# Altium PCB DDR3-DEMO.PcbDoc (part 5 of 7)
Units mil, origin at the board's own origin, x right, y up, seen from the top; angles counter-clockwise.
Board outline 2827 x 2165.35 mil, 8 copper layers (TOP, GND02, ART03, ART04, PWR05, ART06, GND07, BOTTOM); 111 components, 133 nets, 5542 pads, 873 vias.
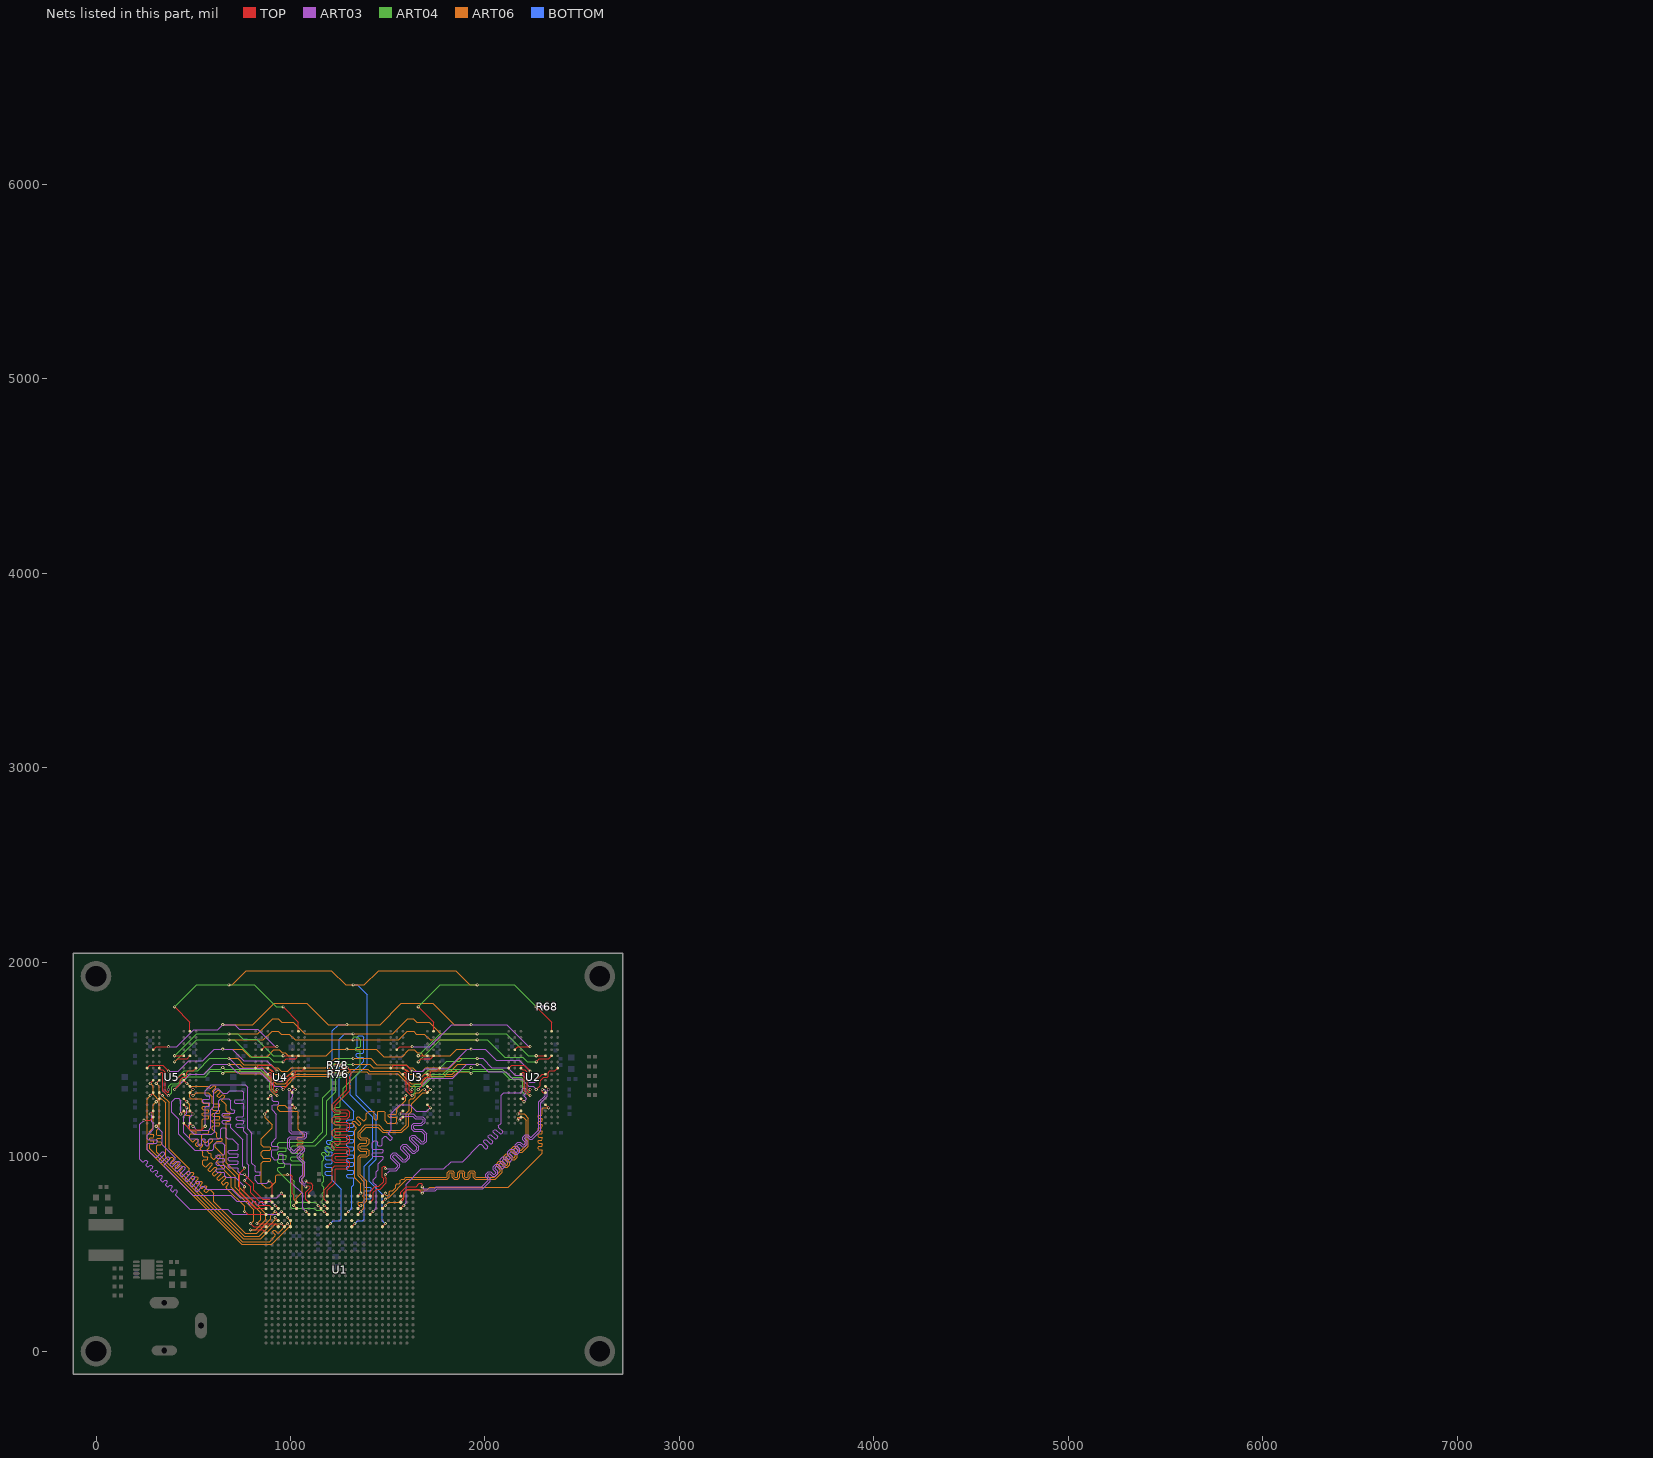
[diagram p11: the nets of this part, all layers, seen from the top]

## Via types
v1: diameter 16, hole 8, TOP to BOTTOM, tented both sides, 873 vias

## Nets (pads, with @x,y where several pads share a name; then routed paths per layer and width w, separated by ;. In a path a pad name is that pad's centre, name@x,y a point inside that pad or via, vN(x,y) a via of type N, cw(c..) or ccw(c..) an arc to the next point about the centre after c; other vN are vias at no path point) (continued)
DRAM_D49: U1.AE22 U5.A7 | length 1355
  TOP w6: v1(309.66,1157.16) U5.A7@325.41,1172.91 ; v1(952.69,813.6) U1.AE22@968.44,797.85
  ART03 w6: v1(309.66,1157.16) 339.42,1127.4 339.42,1062.35 365.92,1035.85 406.79,994.98 406.79,988.61 381.91,963.74 381.91,957.37 388.28,951.01 394.64,951.01 419.52,975.89 425.88,975.89 432.25,969.52 432.25,963.16 407.37,938.28 407.37,931.92 413.73,925.55 420.1,925.55 444.97,950.43 451.34,950.43 457.7,944.07 457.7,937.7 432.82,912.83 432.82,906.46 439.19,900.1 445.55,900.1 470.43,924.98 476.79,924.98 483.16,918.61 483.16,912.25 458.28,887.37 458.28,881.01 464.64,874.64 471.01,874.64 495.89,899.52 502.25,899.52 508.61,893.16 508.61,886.79 483.74,861.91 483.74,855.55 490.1,849.19 496.46,849.19 521.34,874.06 527.71,874.06 534.07,867.7 534.07,861.34 509.19,836.46 509.19,830.09 515.56,823.73 521.92,823.73 546.8,848.61 553.16,848.61 556.34,845.43 568.42,833.35 698.42,833.35 742.42,789.35 928.45,789.35 v1(952.69,813.6)
DRAM_D50: U1.AE24 U5.A3 | length 1355
  TOP w6: U5.A3@451.39,1172.91 484.95,1139.35 543.82,1139.35 v1(561.63,1157.16) ; v1(889.69,876.59) 905.44,860.84 U1.AE24@905.44,797.85
  ART03 w6: v1(561.63,1157.16) 561.63,1255.85 566.13,1260.35 580.89,1260.35 585.39,1264.85 585.39,1273.85 580.89,1278.35 554.13,1278.35 549.63,1282.85 549.63,1291.85 554.13,1296.35 580.89,1296.35 585.39,1300.85 585.39,1309.85 580.89,1314.35 566.13,1314.35 561.63,1318.85 561.63,1338.56 592.42,1369.35 767.42,1369.35 779.42,1357.35 779.42,1143.35 801.42,1121.35 801.42,966.35 817.42,950.35 817.42,926.85 821.92,922.35 840.92,922.35 845.42,917.85 845.42,908.85 840.92,904.35 821.92,904.35 817.42,899.85 817.42,878.35 831.42,864.35 877.46,864.35 v1(889.69,876.59)
DRAM_D51: U1.AC24 U5.C3 | length 1344.5
  TOP w6: v1(435.64,1220.15) U5.C3@451.39,1235.9 ; v1(762.59,846.2) 762.59,819.18 831.16,750.61 889.69,750.61 U1.AC24@905.44,734.86
  ART03 w6: v1(435.64,1220.15) 435.64,1289.13 424.42,1300.35 407.42,1300.35 390.42,1283.35 390.42,1229.35 426.42,1193.35 426.42,1116.35 508.42,1034.35 597.42,1034.35 604.42,1041.35 604.42,1061.35 615.42,1072.35 648.42,1072.35 661.42,1059.35 661.42,1015.85 656.92,1011.35 623.21,1011.35 618.71,1006.85 618.71,997.85 623.21,993.35 656.92,993.35 661.42,988.85 661.42,979.85 656.92,975.35 623.21,975.35 618.71,970.85 618.71,961.85 623.21,957.35 656.92,957.35 661.42,952.85 661.42,943.85 656.92,939.35 623.21,939.35 618.71,934.85 618.71,925.85 623.21,921.35 656.92,921.35 661.42,916.85 661.42,901.35 668.98,893.79 716.98,893.79 762.59,848.18 v1(762.59,846.2)
DRAM_D52: U1.AB22 U5.B8 | length 1355
  TOP w6: v1(246.67,1188.66) 278.16,1188.66 U5.B8@293.91,1204.41 ; v1(952.69,719.11) U1.AB22@968.44,703.36
  ART03 w6: v1(246.67,1188.66) 225.42,1167.41 225.42,986.35 234.68,977.09 237.86,973.91 244.22,973.91 252.54,982.23 258.9,982.23 265.27,975.86 265.27,969.5 256.95,961.18 256.95,954.82 263.31,948.46 269.68,948.46 277.99,956.77 284.36,956.77 290.72,950.41 290.72,944.04 282.4,935.73 282.4,929.36 288.77,923 295.13,923 303.45,931.32 309.81,931.32 316.18,924.95 316.18,918.59 307.86,910.27 307.86,903.91 314.22,897.54 320.59,897.54 328.9,905.86 335.27,905.86 341.63,899.5 341.63,893.13 333.32,884.82 333.32,878.45 339.68,872.09 346.04,872.09 354.36,880.41 360.72,880.41 367.09,874.04 367.09,867.68 358.77,859.36 358.77,853 365.14,846.63 371.5,846.63 379.82,854.95 386.18,854.95 392.54,848.59 392.54,842.22 384.23,833.91 384.23,827.54 390.59,821.18 396.96,821.18 405.27,829.49 411.64,829.49 418,823.13 418,816.77 409.68,808.45 409.68,802.09 460.92,750.85 481.42,730.35 676.42,730.35 703.41,703.36 936.95,703.36 v1(952.69,719.11)
DRAM_D53: U1.AC23 U5.C8 | length 1355
  TOP w6: v1(278.16,1220.15) U5.C8@293.91,1235.9 ; v1(921.19,750.61) U1.AC23@936.94,734.86
  ART03 w6: v1(278.16,1220.15) 287.42,1210.89 287.42,1181.35 293.91,1174.86 293.91,1140.84 264.42,1111.35 264.42,1091.85 268.92,1087.35 309.92,1087.35 314.42,1082.85 314.42,1073.85 309.92,1069.35 268.92,1069.35 264.42,1064.85 264.42,1037.35 305.07,996.7 311.43,996.7 340.42,1025.69 346.79,1025.69 353.15,1019.33 353.15,1012.96 324.16,983.97 324.16,977.61 330.53,971.24 336.89,971.24 365.88,1000.24 372.24,1000.24 378.61,993.87 378.61,987.51 349.62,958.52 349.62,952.15 498.42,803.35 691.42,803.35 724.42,770.35 781.92,770.35 786.42,765.85 786.42,758.74 790.92,754.24 799.92,754.24 804.42,758.74 804.42,765.85 808.92,770.35 817.92,770.35 822.42,765.85 822.42,758.74 826.92,754.24 835.92,754.24 840.42,758.74 840.42,765.85 844.92,770.35 853.92,770.35 858.42,765.85 858.42,758.74 862.92,754.24 871.92,754.24 876.42,758.74 876.42,765.85 880.92,770.35 901.45,770.35 v1(921.19,750.61)
DRAM_D54: U1.AD25 U5.A2 | length 1355
  TOP w6: U5.A2@482.89,1172.91 v1(498.64,1157.16) ; v1(762.59,877.7) 794.87,845.42 794.87,815.9 844.41,766.36 U1.AD25@873.95,766.36
  ART03 w6: v1(498.64,1157.16) 518.45,1137.35 578.42,1137.35 590.42,1149.35 590.42,1241.35 605.42,1256.35 605.42,1338.35 617.42,1350.35 628.42,1350.35 652.42,1326.35 674.42,1326.35 688.42,1340.35 750.42,1340.35 758.42,1332.35 758.42,1319.35 758.42,1310.35 758.42,1296.85 753.92,1292.35 716.92,1292.35 712.42,1287.85 712.42,1278.85 716.92,1274.35 753.92,1274.35 758.42,1269.85 758.42,1265.35 758.42,1236.35 758.42,1209.85 753.92,1205.35 726.44,1205.35 721.94,1200.85 721.94,1191.85 726.44,1187.35 753.92,1187.35 758.42,1182.85 758.42,1173.85 753.92,1169.35 726.44,1169.35 721.94,1164.85 721.94,1155.85 726.44,1151.35 753.92,1151.35 758.42,1146.85 758.42,1142.35 758.42,1132.35 776.42,1114.35 776.42,963.35 784.42,955.35 784.42,899.54 v1(762.59,877.7)
DRAM_D55: U1.AC25 U5.C2 | length 1362
  TOP w6: U5.C2@482.89,1235.9 v1(498.64,1220.15) ; v1(763.71,941.82) 738.42,916.53 738.42,815.35 818.91,734.86 U1.AC25@873.95,734.86
  ART03 w6: v1(498.64,1220.15) 482.89,1204.41 482.89,1168.82 474.42,1160.35 474.42,1146.35 505.42,1115.35 596.18,1115.35 609.42,1128.59 609.42,1220.35 631.42,1242.35 631.42,1288.35 641.42,1298.35 682.42,1298.35 692.42,1288.35 692.42,1246.85 696.92,1242.35 707.79,1242.35 712.29,1237.85 712.29,1228.85 707.79,1224.35 654.63,1224.35 650.13,1219.85 650.13,1210.85 654.63,1206.35 687.92,1206.35 692.42,1201.85 692.42,1192.85 687.92,1188.35 654.63,1188.35 650.13,1183.85 650.13,1174.85 654.63,1170.35 687.92,1170.35 692.42,1165.85 692.42,1149.35 754.42,1087.35 754.42,951.11 v1(763.71,941.82)
DRAM_D56: U1.AB25 U5.E3 | length 1355
  TOP w6: U5.E3@451.39,1298.89 v1(467.14,1283.14) ; v1(763.71,719.11) 779.46,703.36 U1.AB25@873.95,703.36
  ART06 w4.1: v1(467.14,1283.14) 482.89,1267.39 482.89,1242.35 482.89,1234.52 478.86,1230.5 460.91,1230.5 456.89,1226.47 456.89,1218.42 460.91,1214.4 478.86,1214.4 482.89,1210.37 482.89,1206.35 482.89,1142.35 482.89,1138.32 486.91,1134.3 510.86,1134.3 514.89,1130.27 514.89,1122.22 510.86,1118.2 486.91,1118.2 482.89,1114.17 482.89,1102.1 482.89,1098.35 482.89,1089.88 492.42,1080.35 495.27,1077.5 500.96,1077.5 513.65,1090.2 519.34,1090.2 525.04,1084.5 525.04,1078.81 512.34,1066.12 512.34,1060.43 518.03,1054.73 523.73,1054.73 536.42,1067.43 542.11,1067.43 547.8,1061.74 547.8,1056.04 535.11,1043.35 535.11,1037.66 542.42,1030.35 549.42,1023.35 549.42,1008.35 549.42,1004.32 553.44,1000.3 571.39,1000.3 575.42,996.27 575.42,988.22 571.39,984.2 553.44,984.2 549.42,980.17 549.42,973.35 549.42,959.35 557.57,951.2 560.42,948.35 566.11,948.35 587.11,969.36 592.81,969.36 598.5,963.67 598.5,957.98 577.49,936.97 577.49,931.28 583.18,925.58 588.88,925.58 609.88,946.59 615.58,946.59 621.27,940.9 621.27,935.21 600.26,914.2 600.26,908.51 605.95,902.82 611.65,902.82 632.65,923.82 638.34,923.82 644.04,918.13 644.04,912.44 623.03,891.43 623.03,885.74 628.72,880.05 634.41,880.05 655.42,901.05 661.11,901.05 666.81,895.36 666.81,889.67 645.8,868.66 645.8,862.97 651.49,857.28 657.18,857.28 668.94,869.03 674.63,869.03 680.32,863.34 680.32,857.65 668.57,845.89 668.57,840.2 669.42,839.35 763.71,745.06 v1(763.71,719.11)
DRAM_D57: U1.AA21 U5.F8 | length 1355.4
  TOP w6: v1(278.16,1314.64) U5.F8@293.91,1330.39 ; v1(984.18,687.62) U1.AA21@999.93,671.87
  ART06 w4.1: v1(278.16,1314.64) 262.42,1298.9 262.42,1036.35 748.42,550.35 903.42,550.35 999.93,646.86 999.93,671.87 v1(984.18,687.62)
DRAM_D58: U1.Y25 U5.G2 | length 1351.9
  TOP w6: U5.G2@482.89,1361.89 v1(498.64,1346.14) ; v1(795.2,656.12) 810.95,640.37 U1.Y25@873.95,640.37
  ART06 w4.1: v1(498.64,1346.14) 482.89,1330.39 482.89,1306.35 490.35,1298.89 540.42,1298.89 546.42,1292.89 546.42,1279.32 550.44,1275.3 576.39,1275.3 580.42,1271.27 580.42,1263.22 576.39,1259.2 550.44,1259.2 546.42,1255.17 546.42,1247.12 550.44,1243.1 576.39,1243.1 580.42,1239.07 580.42,1231.02 576.39,1227 550.44,1227 546.42,1222.97 546.42,1214.92 550.44,1210.9 576.39,1210.9 580.42,1206.87 580.42,1198.82 576.39,1194.8 550.44,1194.8 546.42,1190.77 546.42,1139.32 550.44,1135.3 576.39,1135.3 580.42,1131.27 580.42,1123.22 576.39,1119.2 550.27,1119.2 542.42,1111.35 542.42,1090.35 557.09,1075.68 569.78,1075.68 588.13,1094.03 593.82,1094.03 599.51,1088.34 599.51,1082.65 581.16,1064.3 581.16,1046.09 571.42,1036.35 571.42,1028.35 580.42,1019.35 588.42,1019.35 592.42,1015.35 592.42,998.35 602.46,988.31 608.16,988.31 627.92,1008.07 633.61,1008.07 639.3,1002.38 639.3,996.68 619.54,976.92 619.54,971.23 696.42,894.35 696.42,842.35 811.42,727.35 811.42,672.33 v1(795.2,656.12)
DRAM_D59: U1.Y22 U5.H8 | length 1355
  TOP w6: v1(278.16,1377.63) U5.H8@293.91,1393.38 ; v1(952.69,656.12) U1.Y22@968.44,640.37
  ART06 w4.1: v1(278.16,1377.63) 293.91,1361.88 293.91,1320.86 325.41,1289.36 325.41,1149.35 313.42,1137.36 313.42,1114.32 317.44,1110.3 332.93,1110.3 336.95,1106.27 336.95,1098.22 332.93,1094.2 317.44,1094.2 313.42,1090.17 313.42,1082.12 317.44,1078.1 332.93,1078.1 336.95,1074.07 336.95,1066.02 332.93,1062 317.44,1062 313.42,1057.97 313.42,1022.4 757.47,578.35 847.42,578.35 925.19,656.12 v1(952.69,656.12)
DRAM_D60: U1.AB23 U5.F7 | length 1355
  TOP w6: U5.F7@325.41,1330.39 v1(341.16,1314.64) ; v1(921.19,719.11) U1.AB23@936.94,703.36
  ART06 w4.1: v1(341.16,1314.64) 375.42,1280.38 375.42,1041.35 479.07,937.7 479.07,932.01 466.25,919.19 466.25,913.49 471.94,907.8 477.64,907.8 490.46,920.62 496.15,920.62 501.84,914.93 501.84,909.24 489.02,896.42 489.02,890.72 494.71,885.03 500.4,885.03 513.22,897.85 518.92,897.85 524.61,892.16 524.61,886.47 511.79,873.65 511.79,867.96 517.48,862.26 523.17,862.26 535.99,875.08 541.69,875.08 547.38,869.39 547.38,863.7 534.56,850.88 534.56,845.19 540.25,839.49 545.94,839.49 558.76,852.31 564.45,852.31 570.15,846.62 570.15,840.93 557.33,828.11 557.33,822.42 563.02,816.73 568.71,816.73 581.53,829.55 587.22,829.55 604.42,812.35 604.42,768.45 766.52,606.35 825.42,606.35 899.42,680.35 899.42,697.33 v1(921.19,719.11)
DRAM_D61: U1.AA23 U5.H7 | length 1355
  TOP w6: v1(309.66,1377.63) U5.H7@325.41,1393.38 ; v1(921.19,687.62) U1.AA23@936.94,671.87
  ART06 w4.1: v1(309.66,1377.63) 325.41,1361.88 325.41,1309.36 357.42,1277.35 357.42,996.93 368.56,985.79 374.25,985.79 387.43,998.97 393.12,998.97 398.81,993.28 398.81,987.59 385.63,974.41 385.63,968.72 391.32,963.02 397.02,963.02 410.2,976.2 415.89,976.2 421.58,970.51 421.58,964.82 408.4,951.64 408.4,945.95 414.09,940.26 419.78,940.26 432.96,953.44 438.66,953.44 444.35,947.74 444.35,942.05 431.17,928.87 431.17,923.18 762,592.35 838.42,592.35 921.19,675.12 v1(921.19,687.62)
DRAM_D62: U1.Y23 U5.F2 | length 1338
  TOP w6: U5.F2@482.89,1330.39 v1(498.64,1314.64) ; v1(826.69,656.12) 921.19,656.12 U1.Y23@936.94,640.37
  ART06 w4.1: v1(498.64,1314.64) 514.38,1330.38 576.38,1330.39 598.42,1308.35 598.42,1276.32 602.44,1272.3 632.39,1272.3 636.42,1268.27 636.42,1260.22 632.39,1256.2 602.44,1256.2 598.42,1252.17 598.42,1244.12 602.44,1240.1 632.39,1240.1 636.42,1236.07 636.42,1228.02 632.39,1224 602.44,1224 598.42,1219.97 598.42,1211.92 602.44,1207.9 632.39,1207.9 636.42,1203.87 636.42,1195.82 632.39,1191.8 602.44,1191.8 598.42,1187.77 598.42,1179.72 602.44,1175.7 632.39,1175.7 636.42,1171.67 636.42,1163.62 632.39,1159.6 602.44,1159.6 598.42,1155.57 598.42,1142.35 620.42,1120.35 620.42,1099.32 624.44,1095.3 644.39,1095.3 648.42,1091.27 648.42,1083.22 644.39,1079.2 624.27,1079.2 612.42,1067.35 612.42,1049.35 654.42,1007.35 654.42,962.35 716.37,900.4 716.37,843.4 847.42,712.35 847.42,676.84 v1(826.69,656.12)
DRAM_D63: U1.W25 U5.H3 | length 1355
  TOP w6: U5.H3@451.39,1393.38 v1(467.14,1377.63) ; v1(795.2,624.63) 858.2,624.63 U1.W25@873.95,608.88
  ART06 w4.1: v1(467.14,1377.63) 482.88,1361.88 573.88,1361.89 581.45,1354.32 584.3,1351.47 589.99,1351.47 604.1,1365.58 609.79,1365.58 615.48,1359.88 615.48,1354.19 601.38,1340.08 601.38,1334.39 607.07,1328.7 612.76,1328.7 626.87,1342.81 632.56,1342.81 638.25,1337.11 638.25,1331.42 624.15,1317.32 624.15,1311.62 629.84,1305.93 635.53,1305.93 649.64,1320.04 655.33,1320.04 661.02,1314.35 661.02,1308.65 646.91,1294.55 646.91,1288.85 655.45,1280.32 666.42,1269.35 669.42,1266.35 669.42,1240.35 669.42,1236.32 673.44,1232.3 685.68,1232.3 689.7,1228.27 689.7,1220.22 685.68,1216.2 669.42,1216.2 661.26,1216.2 657.23,1212.17 657.23,1204.12 661.26,1200.1 669.42,1200.1 685.68,1200.1 689.7,1196.07 689.7,1188.02 685.68,1184 673.44,1184 669.42,1179.97 669.42,1113.35 669.42,969.35 734.42,904.35 734.42,846.35 872.42,708.35 872.42,676.35 820.7,624.63 v1(795.2,624.63)
DRAM_DQM0: U1.AC3 U2.E7 | length 1424.6
  TOP w6: U1.AC3@1566.86,734.86 v1(1582.61,750.61) ; U2.E7@2184.92,1298.89 v1(2200.67,1283.14)
  ART03 w6: v1(1582.61,750.61) 1595.42,763.42 1595.42,859.35 1673.42,937.35 1787.42,937.35 1825.42,975.35 1885.42,975.35 1973.46,1063.39 1979.83,1063.39 2001.75,1041.47 2008.11,1041.47 2014.48,1047.84 2014.48,1054.2 1992.56,1076.12 1992.56,1082.49 1998.92,1088.85 2005.28,1088.85 2027.2,1066.93 2033.57,1066.93 2039.93,1073.29 2039.93,1079.66 2018.01,1101.58 2018.01,1107.94 2024.38,1114.31 2030.74,1114.31 2052.66,1092.39 2059.02,1092.39 2065.39,1098.75 2065.39,1105.11 2043.47,1127.03 2043.47,1133.4 2049.83,1139.76 2056.2,1139.76 2078.12,1117.84 2084.48,1117.84 2090.84,1124.21 2090.84,1130.57 2068.92,1152.49 2068.92,1158.85 2082.42,1172.35 2082.42,1316.35 2096.46,1330.39 2183.38,1330.39 2190.42,1337.43 2190.42,1346.35 2195.42,1351.35 2206.42,1351.35 2212.42,1345.35 2212.42,1330.35 2202.42,1320.35 2202.42,1310.35 2212.42,1300.35 2212.42,1294.89 v1(2200.67,1283.14)
DRAM_DQM1: U1.AC6 U2.D3 | length 1443.3
  TOP w6: U1.AC6@1472.37,734.86 v1(1488.12,750.61) ; U2.D3@2310.9,1267.4 v1(2326.65,1251.65)
  ART06 w4.1: v1(1488.12,750.61) 1503.87,766.36 1557.43,766.36 1584.42,793.35 1584.42,813.35 1601.42,830.35 1703.42,830.35 1716.42,843.35 2120.42,843.35 2295.42,1018.35 2295.42,1033.37 2291.39,1037.4 2277.44,1037.4 2273.42,1041.42 2273.42,1049.47 2277.44,1053.5 2291.39,1053.5 2295.42,1057.52 2295.42,1065.57 2291.39,1069.6 2277.44,1069.6 2273.42,1073.62 2273.42,1081.67 2277.44,1085.7 2291.39,1085.7 2295.42,1089.72 2295.42,1097.77 2291.39,1101.8 2277.44,1101.8 2273.42,1105.82 2273.42,1113.87 2277.44,1117.9 2291.39,1117.9 2295.42,1121.92 2295.42,1129.97 2291.39,1134 2277.44,1134 2273.42,1138.02 2273.42,1146.07 2277.44,1150.1 2291.39,1150.1 2295.42,1154.12 2295.42,1162.17 2291.39,1166.2 2277.44,1166.2 2273.42,1170.22 2273.42,1178.27 2277.44,1182.3 2291.39,1182.3 2295.42,1186.32 2295.42,1194.37 2291.39,1198.4 2277.44,1198.4 2273.42,1202.42 2273.42,1210.47 2277.44,1214.5 2291.39,1214.5 2295.42,1218.52 2295.42,1246.35 2300.72,1251.65 v1(2326.65,1251.65)
DRAM_DQM2: U1.AB8 U3.D3 | length 1150
  TOP w6: U1.AB8@1409.38,703.36 v1(1425.13,719.11) ; U3.D3@1703.89,1267.4 v1(1719.64,1251.65)
  ART03 w6: v1(1425.13,719.11) 1440.88,734.86 1440.88,852.89 1426.42,867.35 1426.42,882.35 1440.88,896.81 1440.88,923.35 1451.42,933.89 1451.42,964.35 1477.42,990.35 1477.42,997.85 1472.92,1002.35 1423.92,1002.35 1419.42,1006.85 1419.42,1015.85 1423.92,1020.35 1472.92,1020.35 1477.42,1024.85 1477.42,1033.85 1472.92,1038.35 1423.92,1038.35 1419.42,1042.85 1419.42,1071.35 1429.42,1081.35 1441.42,1081.35 1448.42,1074.35 1448.42,1059.35 1451.42,1056.35 1465.42,1056.35 1471.42,1062.35 1471.42,1092.35 1484.35,1105.28 1490.71,1105.28 1509.87,1086.12 1516.24,1086.12 1522.6,1092.49 1522.6,1098.85 1503.44,1118.01 1503.44,1124.37 1506.62,1127.55 1517.42,1138.35 1517.42,1223.35 1561.42,1267.35 1613.4,1267.35 1647.18,1233.57 1701.55,1233.57 v1(1719.64,1251.65)
DRAM_DQM3: U1.AE10 U3.E7 | length 1150.2
  TOP w6: U1.AE10@1346.39,797.85 v1(1362.14,813.6) ; U3.E7@1577.91,1298.89 v1(1593.66,1314.64)
  ART06 w4.1: v1(1362.14,813.6) 1362.42,813.88 1362.42,860.35 1329.42,893.35 1329.42,1135.35 1338.77,1144.7 1338.77,1150.39 1317.84,1171.32 1317.84,1177.01 1323.53,1182.7 1329.22,1182.7 1350.15,1161.77 1355.84,1161.77 1361.53,1167.46 1361.53,1173.16 1340.61,1194.09 1340.61,1199.78 1346.3,1205.47 1351.99,1205.47 1372.92,1184.54 1378.61,1184.54 1389.42,1195.35 1389.42,1220.35 1404.42,1235.35 1427.24,1235.35 1431.27,1231.32 1431.27,1195.37 1435.29,1191.35 1443.34,1191.35 1447.37,1195.37 1447.37,1231.32 1451.39,1235.35 1479.42,1235.35 1486.42,1228.35 1486.42,1185.35 1498.42,1173.35 1540.42,1173.35 1547.42,1180.35 1547.42,1199.37 1543.39,1203.4 1507.44,1203.4 1503.42,1207.42 1503.42,1215.47 1507.44,1219.5 1543.39,1219.5 1547.42,1223.52 1547.42,1245.35 1593.66,1291.59 v1(1593.66,1314.64)
DRAM_DQM4: U1.AB18 U4.E7 | length 943.6
  TOP w6: U4.E7@883.39,1298.89 898.63,1314.13 v1(898.63,1314.57) ; v1(1078.67,719.11) U1.AB18@1094.42,703.36
  ART03 w6: v1(898.63,1314.57) 905.42,1307.78 905.42,1290.85 909.92,1286.35 934.92,1286.35 939.42,1281.85 939.42,1272.85 934.92,1268.35 909.92,1268.35 905.42,1263.85 905.42,1241.35 927.42,1219.35 927.42,1098.35 902.42,1073.35 902.42,1057.85 906.92,1053.35 931.92,1053.35 936.42,1048.85 936.42,1039.85 931.92,1035.35 906.92,1035.35 902.42,1030.85 902.42,1000.35 917.42,985.35 932.42,985.35 938.42,991.35 938.42,1011.35 943.42,1016.35 955.42,1016.35 962.42,1009.35 962.42,972.35 969.42,965.35 996.42,965.35 1002.42,959.35 1002.42,870.35 1062.92,809.85 1062.92,734.86 v1(1078.67,719.11)
DRAM_DQM5: U1.AC20 U4.D3 | length 940
  TOP w6: U4.D3@1009.37,1267.4 v1(1025.12,1251.65) ; v1(1015.68,750.61) U1.AC20@1031.43,734.86
  ART06 w4.1: v1(1015.68,750.61) 1028.42,763.34 1028.42,786.35 1059.42,817.35 1059.42,886.35 1065.42,892.35 1065.42,1011.35 1065.42,1015.37 1061.39,1019.4 1037.45,1019.4 1033.42,1023.42 1033.42,1031.47 1037.45,1035.5 1061.39,1035.5 1065.42,1039.52 1065.42,1047.57 1061.39,1051.6 1037.45,1051.6 1033.42,1055.62 1033.42,1063.67 1037.45,1067.7 1061.39,1067.7 1065.42,1071.72 1065.42,1079.77 1061.39,1083.8 1037.45,1083.8 1033.42,1087.82 1033.42,1095.87 1037.45,1099.9 1061.39,1099.9 1065.42,1103.92 1065.42,1109.35 1065.42,1116.8 1040.87,1141.35 1040.87,1227.9 1033.42,1235.35 944.42,1235.35 935.42,1244.35 935.42,1258.35 941.42,1264.35 971.42,1264.35 984.12,1251.65 v1(1025.12,1251.65)
DRAM_DQM6: U1.AD24 U5.D3 | length 1347.4
  TOP w6: U5.D3@451.39,1267.4 v1(467.14,1251.65) ; v1(763.36,909.98) 811.42,861.92 811.42,828.87 858.18,782.11 889.69,782.11 U1.AD24@905.44,766.36
  ART03 w6: v1(467.14,1251.65) 467.14,1223.07 451.39,1207.32 451.39,1123.38 482.42,1092.35 520.92,1092.35 525.42,1087.85 525.42,1061.38 529.92,1056.88 538.92,1056.88 543.42,1061.38 543.42,1087.85 547.92,1092.35 556.92,1092.35 561.42,1087.85 561.42,1061.38 565.92,1056.88 574.92,1056.88 579.42,1061.38 579.42,1087.85 583.92,1092.35 615.42,1092.35 632.92,1092.35 640.42,1099.85 640.42,1142.85 647.92,1150.35 662.92,1150.35 670.42,1142.85 670.42,1099.85 677.92,1092.35 700.42,1092.35 730.42,1062.35 730.42,1037.85 725.92,1033.35 684.92,1033.35 680.42,1028.85 680.42,1019.85 684.92,1015.35 725.92,1015.35 730.42,1010.85 730.42,1001.85 725.92,997.35 684.92,997.35 680.42,992.85 680.42,983.85 684.92,979.35 725.92,979.35 730.42,974.85 730.42,965.85 725.92,961.35 684.92,961.35 680.42,956.85 680.42,947.85 684.92,943.35 725.92,943.35 730.42,938.85 730.42,923.35 743.79,909.98 v1(763.36,909.98)
DRAM_DQM7: U1.Y21 U5.E7 | length 1355
  TOP w6: v1(309.66,1283.14) U5.E7@325.41,1298.89 ; v1(984.18,656.12) U1.Y21@999.93,640.37
  ART06 w4.1: v1(309.66,1283.14) 293.91,1267.39 293.91,1149.35 275.52,1130.96 275.52,1119.32 279.54,1115.3 293.39,1115.3 297.41,1111.27 297.41,1103.22 293.39,1099.2 279.54,1099.2 275.52,1095.17 275.52,1087.12 279.54,1083.1 293.39,1083.1 297.41,1079.07 297.41,1071.02 293.39,1067 279.54,1067 275.52,1062.97 275.52,1041.78 752.95,564.35 892.42,564.35 921.13,593.07 921.13,598.76 908.71,611.18 908.71,616.87 914.4,622.57 920.1,622.57 932.52,610.14 938.21,610.14 v1(984.18,656.12)
DRAM_RAS_B: U1.AB15 U2.J3 U3.J3 U4.J3 U5.J3 | length 4513.2
  TOP w6: v1(404.15,1393.38) 409.45,1393.38 440.95,1424.88 U5.J3@451.39,1424.88 ; v1(962.13,1393.38) 993.63,1424.88 U4.J3@1009.37,1424.88 ; v1(1173.16,719.11) U1.AB15@1188.91,703.36 ; v1(1656.65,1393.38) 1688.15,1424.88 U3.J3@1703.89,1424.88 ; v1(2263.66,1393.38) 2295.16,1424.88 U2.J3@2310.9,1424.88
  ART03 w6: v1(683.14,1506.49) 685.75,1506.49 736.89,1455.35 855.89,1455.35 923.89,1387.35 956.1,1387.35 v1(962.13,1393.38) ; v1(1960.15,1506.49) 1987.28,1506.49 2035.42,1458.35 2116.42,1458.35 2154.89,1419.88 2192.89,1419.88 2228.42,1384.35 2254.63,1384.35 v1(2263.66,1393.38)
  ART04 w6: v1(404.15,1393.38) 404.15,1393.61 453.89,1443.35 521.89,1443.35 585.03,1506.49 v1(683.14,1506.49) ; v1(1173.16,719.11) 1166.66,725.6 1131.67,725.6 1122.42,734.86 1005.91,734.86 999.93,740.84 999.93,860.84 933.42,927.35 933.42,942.35 938.42,947.35 964.89,947.35 969.89,952.35 969.89,962.35 964.89,967.35 938.42,967.35 933.42,972.35 933.42,982.35 938.42,987.35 974.29,987.35 979.29,992.35 979.29,1002.35 974.29,1007.35 938.42,1007.35 933.42,1012.35 933.42,1022.35 938.42,1027.35 974.29,1027.35 979.29,1032.35 979.29,1042.35 974.29,1047.35 938.42,1047.35 933.42,1052.35 933.42,1067.35 941.42,1075.35 1113.42,1075.35 1166.42,1128.35 1166.42,1304.35 1210.42,1348.35 1210.42,1463.35 1253.56,1506.49 v1(1321.64,1506.49) ; v1(1656.65,1393.38) 1714.62,1451.35 1763.42,1451.35 1803.42,1491.35 1871.42,1491.35 1886.56,1506.49 v1(1960.15,1506.49)
  ART06 w4.1: v1(683.14,1506.49) 728.28,1506.49 760.42,1474.35 899.92,1474.35 916.92,1457.35 934.92,1457.35 951.92,1440.35 986.42,1440.35 1003.42,1457.35 1180.91,1457.35 1230.05,1506.49 v1(1321.64,1506.49) 1412.28,1506.49 1444.42,1474.35 1594.42,1474.35 1611.42,1457.35 1629.42,1457.35 1646.42,1440.35 1679.42,1440.35 1696.42,1457.35 1819.42,1457.35 1868.56,1506.49 v1(1960.15,1506.49)
DRAM_RESET_B: R68.2 U1.Y6 U2.T2 U3.T2 U4.T2 U5.T2 | length 4833.4
  TOP w6: v1(404.15,1771.33) 482.89,1692.59 U5.T2@482.89,1645.35 ; v1(962.13,1771.33) 1040.87,1692.59 U4.T2@1040.87,1645.35 ; U1.Y6@1472.37,640.37 v1(1488.12,656.12) ; v1(1656.65,1771.33) 1735.39,1692.59 U3.T2@1735.39,1645.35 ; v1(2263.66,1771.33) 2342.4,1692.59 U2.T2@2342.4,1645.35
  ART04 w6: v1(404.15,1771.33) 517.26,1884.44 v1(683.14,1884.44) 812.33,1884.44 925.44,1771.33 v1(962.13,1771.33) ; v1(1656.65,1771.33) 1769.76,1884.44 v1(1960.15,1884.44) 2150.55,1884.44 v1(2263.66,1771.33)
  ART06 w4.1: v1(683.14,1884.44) 700.51,1884.44 773.42,1957.35 1209.91,1957.35 1282.82,1884.44 v1(1321.65,1884.44) 1379.51,1884.44 1452.42,1957.35 1848.42,1957.35 1921.33,1884.44 v1(1960.15,1884.44)
  BOTTOM w6: v1(1321.65,1884.44) 1344.33,1884.44 1394.42,1834.35 1394.42,1473.35 1337.42,1416.35 1337.42,1316.35 1440.42,1213.35 1440.42,986.35 1405.42,951.35 1405.42,874.35 1472.37,807.4 1472.37,671.86 v1(1488.12,656.12) ; v1(2263.66,1771.33) R68.2@2303.42,1771.35
DRAM_SDBA0: U1.AC15 U2.M2 U3.M2 U4.M2 U5.M2 | length 4577.5
  TOP w6: v1(404.15,1487.88) 420.62,1504.35 467.87,1504.35 U5.M2@482.89,1519.37 ; v1(962.13,1487.88) 978.6,1504.35 1025.85,1504.35 U4.M2@1040.87,1519.37 ; v1(1173.16,750.61) U1.AC15@1188.91,734.86 ; v1(1656.65,1487.88) 1673.12,1504.35 1720.37,1504.35 U3.M2@1735.39,1519.37 ; v1(2263.66,1487.88) 2280.13,1504.35 2327.38,1504.35 U2.M2@2342.4,1519.37
  ART04 w6: v1(404.15,1487.88) 517.26,1600.99 v1(683.14,1600.99) 711.25,1600.99 800.89,1511.35 891.42,1511.35 914.89,1487.88 v1(962.13,1487.88) ; v1(1173.16,750.61) 1162.42,761.35 1162.42,775.35 1169.42,782.35 1169.42,795.35 1162.42,802.35 1162.42,813.35 1170.42,821.35 1170.42,843.35 1162.42,851.35 1162.42,867.35 1170.42,875.35 1170.42,896.35 1162.42,904.35 1162.42,977.35 1170.42,985.35 1170.42,1000.38 1159.66,1011.13 1159.66,1017.5 1166.03,1023.86 1172.39,1023.86 1187.48,1008.77 1193.84,1008.77 1200.21,1015.14 1200.21,1021.5 1179.7,1042.01 1179.7,1048.37 1186.06,1054.74 1192.43,1054.74 1212.94,1034.23 1219.3,1034.23 1225.66,1040.59 1225.66,1046.96 1205.16,1067.46 1205.16,1073.83 1211.52,1080.19 1217.88,1080.19 1238.39,1059.68 1244.75,1059.68 1255.42,1070.35 1255.42,1088.85 1250.92,1093.35 1228.92,1093.35 1224.42,1097.85 1224.42,1106.85 1228.92,1111.35 1250.92,1111.35 1255.42,1115.85 1255.42,1124.85 1250.92,1129.35 1228.92,1129.35 1224.42,1133.85 1224.42,1142.85 1228.92,1147.35 1250.92,1147.35 1255.42,1151.85 1255.42,1160.85 1250.92,1165.35 1228.92,1165.35 1224.42,1169.85 1224.42,1178.85 1228.92,1183.35 1250.92,1183.35 1255.42,1187.85 1255.42,1196.85 1250.92,1201.35 1228.92,1201.35 1224.42,1205.85 1224.42,1214.85 1228.92,1219.35 1250.92,1219.35 1255.42,1223.85 1255.42,1232.85 1250.92,1237.35 1228.92,1237.35 1224.42,1241.85 1224.42,1250.85 1228.92,1255.35 1250.92,1255.35 1255.42,1259.85 1255.42,1291.35 1272.42,1308.35 1272.42,1352.35 1359.42,1439.35 1359.42,1539.85 1354.92,1544.35 1340.72,1544.35 1336.22,1548.85 1336.22,1557.85 1340.72,1562.35 1354.92,1562.35 1360.42,1567.85 1360.42,1600.35 1343.42,1617.35 1326.42,1617.35 1321.65,1612.58 v1(1321.65,1600.99) ; v1(1656.65,1487.88) 1769.76,1600.99 v1(1960.15,1600.99) 2012.78,1600.99 2102.42,1511.35 2192.95,1511.35 2216.42,1487.88 v1(2263.66,1487.88)
  ART06 w4.1: v1(683.14,1600.99) 860.92,1600.99 905.28,1645.35 937.92,1645.35 952.92,1630.35 993.92,1630.35 1023.28,1600.99 v1(1321.65,1600.99) 1555.42,1600.99 1599.78,1645.35 1632.42,1645.35 1647.42,1630.35 1688.42,1630.35 1717.78,1600.99 v1(1960.15,1600.99)
DRAM_SDBA1: U1.Y15 U2.N8 U3.N8 U4.N8 U5.N8 | length 4611.7
  TOP w6: U5.N8@293.91,1550.86 309.67,1566.62 v1(372.65,1566.62) ; U4.N8@851.89,1550.86 867.65,1566.62 v1(930.63,1566.62) ; U1.Y15@1188.91,640.37 v1(1204.66,656.12) ; U3.N8@1546.41,1550.86 1562.17,1566.62 v1(1625.15,1566.62) ; U2.N8@2153.42,1550.86 2169.18,1566.62 v1(2232.16,1566.62)
  ART03 w6: v1(372.65,1566.62) 415.16,1566.62 501.89,1653.35 625.26,1653.35 v1(651.64,1679.73) 712.04,1679.73 735.42,1656.35 831.42,1656.35 921.15,1566.62 v1(930.63,1566.62) ; v1(1625.15,1566.62) 1716.69,1566.62 1829.8,1679.73 v1(1928.65,1679.73) 2111.04,1679.73 2224.15,1566.62 v1(2232.16,1566.62)
  ART06 w4.1: v1(651.64,1679.73) 805.8,1679.73 915.42,1789.35 1083.42,1789.35 1193.04,1679.73 v1(1290.15,1679.73) 1460.8,1679.73 1570.42,1789.35 1732.42,1789.35 1842.04,1679.73 v1(1928.65,1679.73)
  BOTTOM w6: v1(1204.66,656.12) 1220.42,671.88 1253.95,671.88 1260.42,678.35 1260.42,833.35 1215.42,878.35 1215.42,900.35 1210.42,905.35 1183.42,905.35 1178.42,910.35 1178.42,920.35 1183.42,925.35 1210.42,925.35 1215.42,930.35 1215.42,940.35 1210.42,945.35 1183.42,945.35 1178.42,950.35 1178.42,960.35 1183.42,965.35 1210.42,965.35 1215.42,970.35 1215.42,980.35 1210.42,985.35 1183.42,985.35 1178.42,990.35 1178.42,1000.35 1183.42,1005.35 1210.42,1005.35 1215.42,1010.35 1215.42,1020.35 1210.42,1025.35 1183.42,1025.35 1178.42,1030.35 1178.42,1040.35 1183.42,1045.35 1210.42,1045.35 1215.42,1050.35 1215.42,1060.35 1210.42,1065.35 1190.87,1065.35 1185.87,1070.35 1185.87,1080.35 1190.87,1085.35 1210.42,1085.35 1215.42,1090.35 1215.42,1647.35 1247.8,1679.73 v1(1290.15,1679.73)
DRAM_SDBA2: U1.AB12 U2.M3 U3.M3 U4.M3 U5.M3 | length 4470.4
  TOP w6: v1@404.15,1519.37 U5.M3@451.39,1519.37 ; v1(962.13,1519.37) U4.M3@1009.37,1519.37 ; U1.AB12@1283.4,703.36 v1(1299.15,719.11) ; v1@1656.65,1519.37 U3.M3@1703.89,1519.37 ; v1(2263.66,1519.37) U2.M3@2310.9,1519.37
  ART04 w6: v1(404.15,1519.37) 517.26,1632.48 v1(683.14,1632.48) 728.42,1632.48 757.55,1603.35 826.42,1603.35 910.4,1519.37 v1(962.13,1519.37) ; v1(1656.65,1519.37) 1769.76,1632.48 v1(1960.15,1632.48) 2108.29,1632.48 2221.4,1519.37 v1(2263.66,1519.37)
  ART06 w4.1: v1(683.14,1632.48) 831.53,1632.48 908.4,1709.35 936.92,1709.35 953.92,1692.35 1013.42,1692.35 1073.29,1632.48 v1(1321.65,1632.48) 1526.03,1632.48 1602.9,1709.35 1631.42,1709.35 1648.42,1692.35 1712.42,1692.35 1772.29,1632.48 v1(1960.15,1632.48)
  BOTTOM w6: v1(1299.15,719.11) 1314.89,734.85 1314.89,845.35 1325.42,855.88 1325.42,886.35 1320.42,891.35 1293.74,891.35 1288.74,896.35 1288.74,906.35 1293.74,911.35 1320.42,911.35 1325.42,916.35 1325.42,926.35 1320.42,931.35 1293.74,931.35 1288.74,936.35 1288.74,946.35 1293.74,951.35 1320.42,951.35 1325.42,956.35 1325.42,966.35 1320.42,971.35 1293.74,971.35 1288.74,976.35 1288.74,986.35 1293.74,991.35 1320.42,991.35 1325.42,996.35 1325.42,1006.35 1320.42,1011.35 1293.74,1011.35 1288.74,1016.35 1288.74,1026.35 1293.74,1031.35 1320.42,1031.35 1325.42,1036.35 1325.42,1046.35 1320.42,1051.35 1293.74,1051.35 1288.74,1056.35 1288.74,1066.35 1293.74,1071.35 1320.42,1071.35 1325.42,1076.35 1325.42,1086.35 1320.42,1091.35 1293.74,1091.35 1288.74,1096.35 1288.74,1106.35 1293.74,1111.35 1320.42,1111.35 1325.42,1116.35 1325.42,1126.35 1320.42,1131.35 1293.74,1131.35 1288.74,1136.35 1288.74,1146.35 1293.74,1151.35 1320.42,1151.35 1325.42,1156.35 1325.42,1166.35 1320.42,1171.35 1293.74,1171.35 1288.74,1176.35 1288.74,1186.35 1293.74,1191.35 1320.42,1191.35 1325.42,1196.35 1325.42,1235.35 1251.42,1309.35 1251.42,1605.35 1278.55,1632.48 v1(1321.65,1632.48)
DRAM_SDCKE0: U1.Y11 U2.K9 U3.K9 U4.K9 U5.K9 | length 4710
  TOP w6: U5.K9@262.42,1456.37 277.4,1471.35 341.93,1471.35 v1(372.65,1440.62) ; U4.K9@820.4,1456.37 835.38,1471.35 899.91,1471.35 v1(930.63,1440.62) ; U1.Y11@1314.89,640.37 v1(1330.64,656.12) ; U3.K9@1514.92,1456.37 1529.9,1471.35 1594.43,1471.35 v1(1625.15,1440.62) ; U2.K9@2121.93,1456.37 2136.91,1471.35 2201.44,1471.35 v1(2232.16,1440.62)
  ART03 w6: v1(372.65,1440.62) 423.42,1440.62 477.15,1494.35 548.89,1494.35 608.27,1553.73 v1(651.64,1553.73) 700.51,1553.73 759.89,1494.35 876.9,1494.35 v1(930.63,1440.62) ; v1(1625.15,1440.62) 1679.69,1440.62 1692.42,1453.35 1809.42,1453.35 1909.8,1553.73 v1(1928.65,1553.73) 2002.04,1553.73 2058.42,1497.35 2175.43,1497.35 v1(2232.16,1440.62)
  ART06 w4.1: v1(651.64,1553.73) 753.04,1553.73 791.42,1515.35 879.39,1515.35 914.39,1550.35 940.92,1550.35 956.92,1534.35 973.92,1534.35 988.92,1519.35 1182.91,1519.35 1217.29,1553.73 v1(1290.15,1553.73) 1441.42,1553.73 1479.8,1515.35 1573.89,1515.35 1608.89,1550.35 1635.42,1550.35 1651.42,1534.35 1668.42,1534.35 1683.42,1519.35 1821.42,1519.35 1855.8,1553.73 v1(1928.65,1553.73)
  BOTTOM w6: v1(1290.15,1553.73) 1334.04,1553.73 1343.42,1563.11 1343.42,1615.35 1350.42,1622.35 1369.42,1622.35 1376.42,1615.35 1376.42,1537.35 1371.42,1532.35 1343.42,1532.35 1338.42,1527.35 1338.42,1517.35 1343.42,1512.35 1371.42,1512.35 1376.42,1507.35 1376.42,1492.35 1307.42,1423.35 1307.42,1319.35 1422.42,1204.35 1422.42,996.35 1377.88,951.81 1377.88,849.35 1382.88,844.35 1409.96,844.35 1414.96,839.35 1414.96,829.35 1409.96,824.35 1382.88,824.35 1377.88,819.35 1377.88,809.35 1382.88,804.35 1410.88,804.35 1415.88,799.35 1415.88,789.35 1410.88,784.35 1382.88,784.35 1377.88,779.35 1377.88,679.35 1370.4,671.87 1346.39,671.87 v1(1330.64,656.12)
DRAM_SDCKE1: U1.AA11
DRAM_SDCLK0: R76.1 U1.AD15 U2.J7 U3.J7 U4.J7 U5.J7 | length 4935.1
  TOP w4.5: U5.J7@325.41,1424.88 334.89,1434.36 338.32,1434.36 343.42,1429.26 343.42,1339.35 368.13,1314.64 v1(372.66,1314.64) ; U4.J7@883.39,1424.88 892.87,1434.36 896.3,1434.36 901.4,1429.26 901.4,1339.35 926.11,1314.64 v1(930.64,1314.64) ; U1.AD15@1188.91,766.36 1173.37,781.9 1173.37,831.3 1215.24,873.17 1215.24,941.15 1227.19,953.1 1286.42,953.1 1290.47,957.15 1290.47,967.55 1286.42,971.6 1227.19,971.6 1215.24,983.55 1215.24,1005.15 1227.19,1017.1 1286.42,1017.1 1290.47,1021.15 1290.47,1031.55 1286.42,1035.6 1227.19,1035.6 1215.24,1047.55 1215.24,1069.15 1227.19,1081.1 1286.42,1081.1 1290.47,1085.15 1290.47,1095.55 1286.42,1099.6 1227.19,1099.6 1215.24,1111.55 1215.24,1133.15 1227.19,1145.1 1286.42,1145.1 1290.47,1149.15 1290.47,1159.55 1286.42,1163.6 1227.19,1163.6 1215.24,1175.55 1215.24,1197.15 1227.19,1209.1 1286.42,1209.1 1290.47,1213.15 1290.47,1223.55 1286.42,1227.6 1227.19,1227.6 1215.24,1239.55 1215.24,1269.67 1290.16,1344.59 v1(1290.16,1427.75) 1262.82,1427.75 R76.1@1260.42,1425.35 ; U3.J7@1577.91,1424.88 1587.39,1434.36 1590.82,1434.36 1595.92,1429.26 1595.92,1339.35 1620.63,1314.64 v1(1625.16,1314.64) ; U2.J7@2184.92,1424.88 2194.4,1434.36 2197.83,1434.36 2202.93,1429.26 2202.93,1339.35 2227.64,1314.64 v1(2232.17,1314.64)
  ART04 w4.5: v1(372.66,1314.64) 388.42,1330.4 388.42,1358.35 394.92,1364.85 423.77,1364.85 471.77,1412.85 561.77,1412.85 588.27,1439.35 640.06,1439.35 v1(651.65,1427.75) 663.25,1439.35 840.04,1439.35 893.39,1386 893.39,1345.09 913.34,1325.14 920.14,1325.14 v1(930.64,1314.64) ; v1(1625.16,1314.64) 1641.42,1330.9 1641.42,1357.35 1647.92,1363.85 1682.92,1363.85 1731.92,1412.85 1787.77,1412.85 1814.27,1439.35 1917.07,1439.35 v1(1928.67,1427.75) 1940.26,1439.35 2085.57,1439.35 2127.07,1397.85 2183.07,1397.85 2194.92,1386 2194.92,1332.29 2202.07,1325.14 2221.67,1325.14 v1(2232.17,1314.64)
  ART06 w5: v1(651.65,1427.75) 661.4,1437.5 728.27,1437.5 739.42,1426.35 858.95,1426.35 921.95,1363.35 976.89,1363.35 1026.89,1413.35 1198.88,1413.35 1222.88,1437.35 1266.91,1437.35 ; 1277.91,1437.35 1266.91,1437.35 ; 1916.42,1437.35 1905.42,1437.35 ; v1(1928.67,1427.75) 1919.07,1437.35 1905.42,1437.35 ; 1266.91,1437.35 1280.56,1437.35 v1(1290.16,1427.75) 1299.91,1437.5 1393.27,1437.5 1402.42,1428.35 1551.45,1428.35 1616.45,1363.35 1671.39,1363.35 1721.39,1413.35 1837.39,1413.35 1861.39,1437.35 1905.42,1437.35
DRAM_SDCLK0_B: R78.2 U1.AE15 U2.K7 U3.K7 U4.K7 U5.K7 | length 4962.2
  TOP w4.5: U5.K7@325.41,1456.37 333.92,1447.86 343.91,1447.86 356.92,1434.85 356.92,1341.85 366.42,1332.35 370.42,1332.35 372.66,1334.59 v1(372.66,1346.14) v1@373.42,1345.38 ; U4.K7@883.39,1456.37 891.9,1447.86 901.89,1447.86 914.9,1434.85 914.9,1341.85 924.4,1332.35 928.4,1332.35 930.64,1334.59 v1(930.64,1346.14) v1@931.4,1345.38 ; U1.AE15@1188.91,797.85 1188.91,827.75 1228.74,867.58 1228.74,935.55 1232.79,939.6 1292.01,939.6 1303.97,951.55 1303.97,973.15 1292.01,985.1 1232.79,985.1 1228.74,989.15 1228.74,999.55 1232.79,1003.6 1292.01,1003.6 1303.97,1015.55 1303.97,1037.15 1292.01,1049.1 1232.79,1049.1 1228.74,1053.15 1228.74,1063.55 1232.79,1067.6 1292.01,1067.6 1303.97,1079.55 1303.97,1101.15 1292.01,1113.1 1232.79,1113.1 1228.74,1117.15 1228.74,1127.55 1232.79,1131.6 1292.01,1131.6 1303.97,1143.55 1303.97,1165.15 1292.01,1177.1 1232.79,1177.1 1228.74,1181.15 1228.74,1191.55 1232.79,1195.6 1292.01,1195.6 1303.97,1207.55 1303.97,1229.15 1292.01,1241.1 1232.79,1241.1 1228.74,1245.15 1228.74,1264.08 1303.66,1339 1303.66,1344.59 1308.42,1349.35 1308.42,1362.59 1303.66,1367.35 1303.66,1380.59 1307.42,1384.35 1307.42,1396.59 1303.66,1400.35 1303.66,1410.59 1313.42,1420.35 1313.42,1429.35 1306.42,1436.35 1306.42,1442.99 v1(1290.16,1459.25) 1271.09,1459.25 R78.2@1259.7,1470.63 ; U3.K7@1577.91,1456.37 1586.42,1447.86 1596.41,1447.86 1609.42,1434.85 1609.42,1341.85 1618.92,1332.35 1622.92,1332.35 1625.16,1334.59 v1(1625.16,1346.14) v1@1625.92,1345.38 ; U2.K7@2184.92,1456.37 2193.43,1447.86 2203.42,1447.86 2216.43,1434.85 2216.43,1341.85 2225.93,1332.35 2229.93,1332.35 2232.17,1334.59 v1(2232.17,1346.14) v1@2232.93,1345.38
  ART04 w4.5: v1(372.66,1346.14) 372.66,1361.59 386.42,1375.35 419.42,1375.35 467.42,1423.35 557.42,1423.35 583.92,1449.85 642.25,1449.85 v1(651.65,1459.25) 661.05,1449.85 844.39,1449.85 903.89,1390.35 903.89,1348.88 917.13,1335.64 920.14,1335.64 v1(930.64,1346.14) ; v1(1625.16,1346.14) 1625.16,1359.09 1640.42,1374.35 1678.57,1374.35 1727.57,1423.35 1783.42,1423.35 1809.92,1449.85 1907.91,1449.85 ; 1914.91,1449.85 1907.91,1449.85 ; 1942.42,1449.85 1949.42,1449.85 ; v1(2232.17,1346.14) 2221.67,1335.64 2206.42,1335.64 2205.42,1336.64 2205.42,1390.35 2187.42,1408.35 2131.42,1408.35 2089.92,1449.85 1949.42,1449.85 ; 1907.91,1449.85 1919.27,1449.85 v1(1928.67,1459.25) 1938.06,1449.85 1949.42,1449.85
  ART06 w5: v1(651.65,1459.25) 661.4,1449.5 733.24,1449.5 744.39,1438.35 863.92,1438.35 926.92,1375.35 971.92,1375.35 1021.92,1425.35 1193.91,1425.35 1217.91,1449.35 1280.26,1449.35 v1(1290.16,1459.25) 1299.91,1449.5 1398.24,1449.5 1407.39,1440.35 1556.42,1440.35 1621.42,1375.35 1666.42,1375.35 1716.42,1425.35 1832.42,1425.35 1856.42,1449.35 1918.77,1449.35 v1(1928.67,1459.25)
DRAM_SDODT0: U1.AC16 U2.K1 U3.K1 U4.K1 U5.K1 | length 4882.7
  TOP w6: v1(404.14,1346.14) 433.42,1375.42 433.42,1397.35 445.42,1409.35 460.42,1409.35 466.42,1415.35 466.42,1433.35 474.42,1441.35 499.36,1441.35 U5.K1@514.38,1456.37 ; v1(962.12,1346.14) 982.4,1366.42 982.4,1393.35 998.4,1409.35 1018.4,1409.35 1024.4,1415.35 1024.4,1433.35 1032.4,1441.35 1057.34,1441.35 U4.K1@1072.36,1456.37 ; v1(1141.66,750.61) U1.AC16@1157.41,734.86 ; v1(1656.64,1346.14) 1676.92,1366.42 1676.92,1393.35 1692.92,1409.35 1712.92,1409.35 1718.92,1415.35 1718.92,1433.35 1726.92,1441.35 1751.86,1441.35 U3.K1@1766.88,1456.37 ; v1(2263.65,1346.14) 2283.93,1366.42 2283.93,1390.86 2302.42,1409.35 2319.93,1409.35 2325.93,1415.35 2325.93,1433.35 2333.93,1441.35 2358.87,1441.35 U2.K1@2373.89,1456.37
  ART03 w6: v1(404.14,1346.14) 482.35,1424.35 554.89,1424.35 605.53,1474.99 v1(683.13,1474.99) 725.77,1432.35 846.89,1432.35 917.36,1361.88 946.38,1361.88 v1(962.12,1346.14) ; v1(1656.64,1346.14) 1713.85,1403.35 1835.42,1403.35 1907.06,1474.99 v1(1960.15,1474.99) 1977.78,1474.99 2016.42,1436.35 2107.42,1436.35 2142.71,1401.06 2185.71,1401.06 2224.89,1361.88 2247.91,1361.88 v1(2263.65,1346.14)
  ART04 w6: v1(1141.66,750.61) 1125.92,766.35 1027.42,766.35 1018.42,775.35 1018.42,874.35 1002.42,890.35 1002.42,954.35 1007.42,959.35 1061.42,959.35 1066.42,964.35 1066.42,974.35 1061.42,979.35 1007.42,979.35 1002.42,984.35 1002.42,994.35 1007.42,999.35 1061.42,999.35 1066.42,1004.35 1066.42,1014.35 1061.42,1019.35 1007.42,1019.35 1002.42,1024.35 1002.42,1047.35 1011.92,1056.85 1125.92,1056.85 1185.42,1116.35 1185.42,1288.35 1232.42,1335.35 1232.42,1403.85 1236.92,1408.35 1263.92,1408.35 1268.42,1412.85 1268.42,1421.85 1263.92,1426.35 1236.92,1426.35 1232.42,1430.85 1232.42,1449.35 1258.06,1474.99 v1(1321.64,1474.99)
  ART06 w4.1: v1(683.13,1474.99) 738.78,1474.99 756.42,1457.35 884.92,1457.35 917.92,1424.35 938.92,1424.35 954.92,1408.35 979.92,1408.35 1013.92,1442.35 1187.91,1442.35 1220.55,1474.99 v1(1321.64,1474.99) 1406.78,1474.99 1424.42,1457.35 1579.42,1457.35 1612.42,1424.35 1633.42,1424.35 1649.42,1408.35 1674.42,1408.35 1708.42,1442.35 1826.42,1442.35 1859.06,1474.99 v1(1960.15,1474.99)
DRAM_SDODT1: U1.AB17
DRAM_SDQS0: U1.AE3 U2.F3 | length 1445
  TOP w4.5: U1.AE3@1566.86,797.85 1566.86,817.88 1595.83,846.85 1646.42,846.85 1662.92,863.35 1673.42,863.35 1677.1,859.67 v1(1677.1,845.11) ; v1(2295.15,1346.14) 2295.15,1333.62 2298.38,1330.39 U2.F3@2310.9,1330.39
  ART03 w4.5: v1(1677.1,845.11) 1685.85,836.35 1740.42,836.35 1750.42,846.35 1984.42,846.35 2016.33,878.26 2016.33,883.46 2003.25,896.54 2003.25,910.44 2015.87,923.06 2029.77,923.06 2042.85,909.98 2048.05,909.98 2054.52,916.45 2054.52,921.64 2041.43,934.72 2041.43,948.62 2054.06,961.24 2067.95,961.24 2081.03,948.16 2086.23,948.16 2092.7,954.63 2092.7,959.83 2079.62,972.91 2079.62,986.8 2092.24,999.42 2106.13,999.42 2119.22,986.34 2124.41,986.34 2130.88,992.81 2130.88,998.01 2117.8,1011.09 2117.8,1024.99 2130.42,1037.61 2144.32,1037.61 2157.4,1024.53 2162.6,1024.53 2169.07,1031 2169.07,1036.19 2155.99,1049.28 2155.99,1063.17 2168.61,1075.79 2182.5,1075.79 2195.58,1062.71 2200.78,1062.71 2207.25,1069.18 2207.25,1074.38 2194.17,1087.46 2194.17,1101.35 2206.79,1113.98 2220.69,1113.98 2233.77,1100.89 2238.96,1100.89 2276.42,1138.35 2276.42,1282.2 2308.92,1314.7 2308.92,1342.85 2305.63,1346.14 v1(2295.15,1346.14)
DRAM_SDQS0_B: U1.AD3 U2.G3 | length 1447.7
  TOP w4.5: U1.AD3@1566.86,766.36 1582.61,782.11 1582.61,814.54 1601.42,833.35 1657.36,833.35 v1(1677.1,813.62) ; U2.G3@2310.9,1361.89 v1(2326.65,1346.14)
  ART03 w4.5: v1(1677.1,813.62) 1689.33,825.85 1744.77,825.85 1754.77,835.85 1988.77,835.85 2026.83,873.91 2026.83,887.81 2013.75,900.89 2013.75,906.09 2020.22,912.56 2025.42,912.56 2038.5,899.48 2052.39,899.48 2065.02,912.1 2065.02,925.99 2051.93,939.07 2051.93,944.27 2058.41,950.74 2063.6,950.74 2076.68,937.66 2090.58,937.66 2103.2,950.28 2103.2,964.18 2090.12,977.26 2090.12,982.45 2096.59,988.92 2101.79,988.92 2114.87,975.84 2128.76,975.84 2141.38,988.46 2141.38,1002.36 2128.3,1015.44 2128.3,1020.64 2134.77,1027.11 2139.97,1027.11 2153.05,1014.03 2166.95,1014.03 2179.57,1026.65 2179.57,1040.54 2166.49,1053.62 2166.49,1058.82 2172.96,1065.29 2178.15,1065.29 2191.23,1052.21 2205.13,1052.21 2217.75,1064.83 2217.75,1078.73 2204.67,1091.81 2204.67,1097.01 2211.14,1103.48 2216.34,1103.48 2229.42,1090.39 2243.31,1090.39 2286.92,1134 2286.92,1277.85 2319.42,1310.35 2319.42,1338.91 v1(2326.65,1346.14)
DRAM_SDQS1: U1.AD6 U2.C7 | length 1455.5
  TOP w4.5: U1.AD6@1472.37,766.36 v1(1488.12,782.11) ; v1(2169.17,1220.15) U2.C7@2184.92,1235.9
  ART06 w4.5: v1(1488.12,782.11) 1496.36,790.35 1504.27,790.35 1597.77,883.85 1806.34,883.85 1816.17,893.68 1816.17,913.18 1819.84,916.86 1829,916.86 1832.67,913.18 1832.67,893.68 1842.5,883.85 1860.34,883.85 1870.17,893.68 1870.17,913.18 1873.84,916.86 1883,916.86 1886.67,913.18 1886.67,893.68 1896.5,883.85 1914.34,883.85 1924.17,893.68 1924.17,913.18 1927.84,916.86 1937,916.86 1940.67,913.18 1940.67,893.68 1950.5,883.85 2052.77,883.85 2089.91,920.99 2089.91,934.88 2069.75,955.04 2069.75,960.23 2076.23,966.7 2081.42,966.7 2101.57,946.55 2115.47,946.55 2128.09,959.17 2128.09,973.07 2107.94,993.22 2107.94,998.42 2114.41,1004.89 2119.61,1004.89 2139.76,984.73 2153.65,984.73 2166.27,997.36 2166.27,1011.25 2146.12,1031.4 2146.12,1036.6 2152.59,1043.07 2157.79,1043.07 2177.94,1022.92 2191.84,1022.92 2223.42,1054.5 2223.42,1199.35 2202.62,1220.15 v1(2169.17,1220.15)
DRAM_SDQS1_B: U1.AE6 U2.B7 | length 1456.9
  TOP w4.5: U1.AE6@1472.37,797.85 v1(1488.12,813.6) ; v1(2169.17,1188.66) U2.B7@2184.92,1204.41
  ART06 w4.5: v1(1488.12,813.6) 1488.12,804.65 1491.42,801.35 1500.42,801.35 1506.42,807.35 ; 1524.42,825.35 1540.92,841.85 ; 1559.92,860.85 1565.42,866.35 ; 1584.92,885.85 1593.42,894.35 1802,894.35 1805.67,898.02 1805.67,917.53 1815.5,927.36 1833.34,927.36 1843.17,917.53 1843.17,898.02 1846.84,894.35 1856,894.35 1859.67,898.02 1859.67,917.53 1869.5,927.36 1887.34,927.36 1897.17,917.53 1897.17,898.02 1900.84,894.35 1910,894.35 1913.67,898.02 1913.67,917.53 1923.5,927.36 1941.34,927.36 1951.17,917.53 1951.17,898.02 1954.84,894.35 2048.42,894.35 2079.41,925.34 2079.41,930.53 2059.25,950.69 2059.25,964.58 2071.88,977.2 2085.77,977.2 2105.92,957.05 2111.12,957.05 2117.59,963.52 2117.59,968.72 2097.44,988.87 2097.44,1002.77 2110.06,1015.39 2123.96,1015.39 2144.11,995.23 2149.3,995.23 2155.77,1001.7 2155.77,1006.9 2135.62,1027.05 2135.62,1040.95 2148.24,1053.57 2162.14,1053.57 2182.29,1033.42 2187.49,1033.42 2212.92,1058.85 2212.92,1187.85
  ART06 w5: 1506.42,807.35 1506.42,819.35 1512.42,825.35 1524.42,825.35 ; 1540.92,841.85 1540.92,854.85 1546.92,860.85 1559.92,860.85 ; 1565.42,866.35 1565.42,879.35 1571.92,885.85 1584.92,885.85 ; v1(2169.17,1188.66) 2169.42,1188.91 2169.42,1201.35 2172.2,1204.13 2196.64,1204.13 2212.92,1187.85
DRAM_SDQS2: U1.AD8 U3.C7 | length 1184.7
  TOP w4.5: U1.AD8@1409.38,766.36 1425.42,782.4 1425.42,817.26 1442.51,834.35 1460.51,834.35 1491.92,865.76 1491.92,890.85 1487.42,895.35 v1@1487.42,907.4 ; v1(1562.16,1220.15) U3.C7@1577.91,1235.9
  ART03 w4.5: v1(1488.11,908.09) 1509.1,929.08 1542.99,929.08 1562.01,948.09 1562.01,961.99 1526.3,997.69 1526.3,1002.89 1532.77,1009.36 1537.97,1009.36 1563.34,983.99 1573.68,973.65 1593.72,973.65 1614.21,994.14 1614.21,1007.18 1578.5,1042.89 1578.5,1048.09 1584.97,1054.56 1590.16,1054.56 1625.87,1018.85 1639.77,1018.85 1658.42,1037.5 1658.42,1040.35 1658.42,1054.24 1622.71,1089.95 1622.71,1095.15 1629.18,1101.62 1634.38,1101.62 1670.09,1065.91 1685.98,1065.91 1700.42,1080.35 1700.42,1118.2 1676.77,1141.85 1637.92,1141.85 1632.92,1146.85 1632.92,1158 1636.77,1161.85 1675.77,1161.85 1692.72,1178.8 1692.72,1194.05 1680.42,1206.35 1645.42,1206.35 1631.62,1220.15 v1(1562.16,1220.15)
DRAM_SDQS2_B: U1.AE8 U3.B7 | length 1186.4
  TOP w4.5: U1.AE8@1409.38,797.85 1409.38,820.31 1436.92,847.85 1454.92,847.85 1478.42,871.35 1478.42,889.35 1472.42,895.35 1472.42,945.35 1478.42,951.35 1484.42,951.35 1488.11,947.66 v1(1488.11,939.58) ; v1(1562.16,1188.66) U3.B7@1577.91,1204.41
  ART03 w4.5: v1(1488.11,939.58) 1538.65,939.58 1551.51,952.44 1551.51,957.64 1515.8,993.35 1515.8,1007.24 1528.42,1019.86 1542.32,1019.86 1570.76,991.42 1578.03,984.15 1590.22,984.15 1603.71,997.64 1603.71,1002.83 1568,1038.54 1568,1052.44 1580.62,1065.06 1594.51,1065.06 1630.22,1029.35 1637.42,1029.35 1647.92,1039.85 1647.92,1049.9 1612.21,1085.6 1612.21,1099.5 1624.83,1112.12 1638.73,1112.12 1674.44,1076.41 1681.63,1076.41 1689.92,1084.7 1689.92,1113.85 1672.42,1131.35 1633.57,1131.35 1622.42,1142.5 1622.42,1162.35 1632.42,1172.35 1671.42,1172.35 1682.22,1183.15 1682.22,1189.7 1676.07,1195.85 1641.07,1195.85 1627.27,1209.65 1573.72,1209.65 1562.16,1198.09 v1(1562.16,1188.66)
DRAM_SDQS3: U1.AC10 U3.F3 | length 1150.2
  TOP w4.5: U1.AC10@1346.39,734.86 v1(1362.14,750.61) ; v1(1688.14,1346.14) U3.F3@1703.89,1330.39
  ART06 w5: v1(1362.14,750.61) 1349.16,750.61 1347.42,752.35 1347.42,762.35 1351.42,766.35 1370.42,766.35 1380.42,776.35 1380.42,788.35 1374.42,794.35 1374.42,801.35 1380.42,807.35 1380.42,869.35 1347.42,902.35 1347.42,1001.09 1358.18,1011.85 1388.24,1011.85 1391.98,1015.59 1391.98,1025.11 1388.24,1028.85 1358.18,1028.85 1347.42,1039.61 1347.42,1059.09 1358.18,1069.85 1388.24,1069.85 1391.98,1073.59 1391.98,1083.11 1388.24,1086.85 1358.18,1086.85 1347.42,1097.61 1347.42,1126.35 1385.42,1164.35 1452.42,1164.35 1479.42,1137.35 1567.42,1137.35 1595.42,1165.35 1595.42,1223.85 1610.42,1238.85 1610.42,1291.35 1617.42,1298.35 1631.42,1298.35 1642.42,1309.35 1642.42,1325.35 1646.42,1329.35 1662.42,1329.35 1679.21,1346.14 v1(1688.14,1346.14)
DRAM_SDQS3_B: U1.AB10 U3.G3 | length 1149.8
  TOP w4.5: U1.AB10@1346.39,703.36 v1(1362.14,719.11) ; U3.G3@1703.89,1361.89 v1(1719.64,1346.14)
  ART06 w4.5: v1(1362.14,719.11) 1377.57,734.54 1377.57,758.5 1382.92,763.85
  ART06 w5: 1382.92,763.85 1392.42,773.35 1392.42,874.32 1359.42,907.32 1359.42,996.11 1363.16,999.85 1393.22,999.85 1403.98,1010.61 1403.98,1030.09 1393.22,1040.85 1363.16,1040.85 1359.42,1044.59 1359.42,1054.11 1363.16,1057.85 1393.22,1057.85 1403.98,1068.61 1403.98,1088.09 1393.22,1098.85 1363.16,1098.85 1359.42,1102.59 1359.42,1121.38 1390.39,1152.35 1447.45,1152.35 1474.45,1125.35 1572.39,1125.35 1607.42,1160.38 1607.42,1218.88 1622.42,1233.88 1622.42,1272.38 1680.43,1330.39 1703.89,1330.39 v1(1719.64,1346.14)
DRAM_SDQS4: U1.AD18 U4.F3 | length 942.3
  TOP w4.5: v1(993.62,1346.14) U4.F3@1009.37,1330.39 ; v1(1078.67,845.1) 1085.93,852.35 1097.42,852.35 1101.42,848.35 1101.42,841.35 1078.67,818.6 1078.67,782.11 U1.AD18@1094.42,766.36
  ART03 w4.5: v1(993.62,1346.14) 993.42,1345.94 993.42,1129.43 1003.25,1119.6 1069.75,1119.6 1073.42,1115.93 1073.42,1106.77 1069.75,1103.1 996.17,1103.1 985.42,1092.35 985.42,1044.5 1009.89,1020.03 1023.79,1020.03 1050.99,1047.22 1056.19,1047.22 1062.66,1040.75 1062.66,1035.56 1035.46,1008.36 1035.46,994.46 1062.42,967.5 1062.42,907.2 1046.92,891.7 1046.92,872.85 1074.67,845.1 v1(1078.67,845.1)
DRAM_SDQS4_B: U1.AE18 U4.G3 | length 940.2
  TOP w4.5: U4.G3@1009.37,1361.89 v1(1025.12,1346.14) ; v1(1078.67,876.59) 1089.42,865.85 1103.01,865.85 1114.92,853.94 1114.92,835.76 1094.42,815.26 U1.AE18@1094.42,797.85
  ART03 w4.5: v1(1025.12,1346.14) 1017.21,1346.14 1003.92,1332.85 1003.92,1327.35 1012.42,1318.85 1012.42,1310.35 1003.92,1301.85 1003.92,1133.77 1007.59,1130.1 1074.09,1130.1 1083.92,1120.27 1083.92,1102.43 1074.09,1092.6 1000.52,1092.6 995.92,1088 995.92,1048.85 1014.24,1030.53 1019.44,1030.53 1046.64,1057.72 1060.53,1057.72 1073.16,1045.1 1073.16,1031.21 1045.96,1004.01 1045.96,998.81 1072.92,971.85 1072.92,902.85 1057.42,887.35 1057.42,876.35 1071.42,862.35 1075.42,862.35 1078.67,865.6 v1(1078.67,876.59)
DRAM_SDQS5: U1.AD20 U4.C7 | length 940.8
  TOP w4.5: v1(867.64,1220.15) U4.C7@883.39,1235.9 ; v1(984.19,908.11) 1001.66,908.11 1009.92,899.85 1009.92,811.31 1016.42,804.81 1016.42,781.37 U1.AD20@1031.43,766.36
  ART06 w5: v1(867.64,1220.15) 870.42,1217.37 870.42,1200.38 905.42,1165.38 905.42,1149.35 849.42,1093.35 849.42,1062.61 860.18,1051.85 894.33,1051.85 898.07,1048.11 898.07,1038.59 894.33,1034.85 860.18,1034.85 849.42,1024.09 849.42,1004.61 860.18,993.85 894.33,993.85 898.07,990.11 898.07,980.59 894.33,976.85 860.18,976.85 849.42,966.09 849.42,862.38 871.45,840.35 893.42,840.35 924.42,871.35 924.42,901.38 931.39,908.35 983.95,908.35 v1(984.19,908.11)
